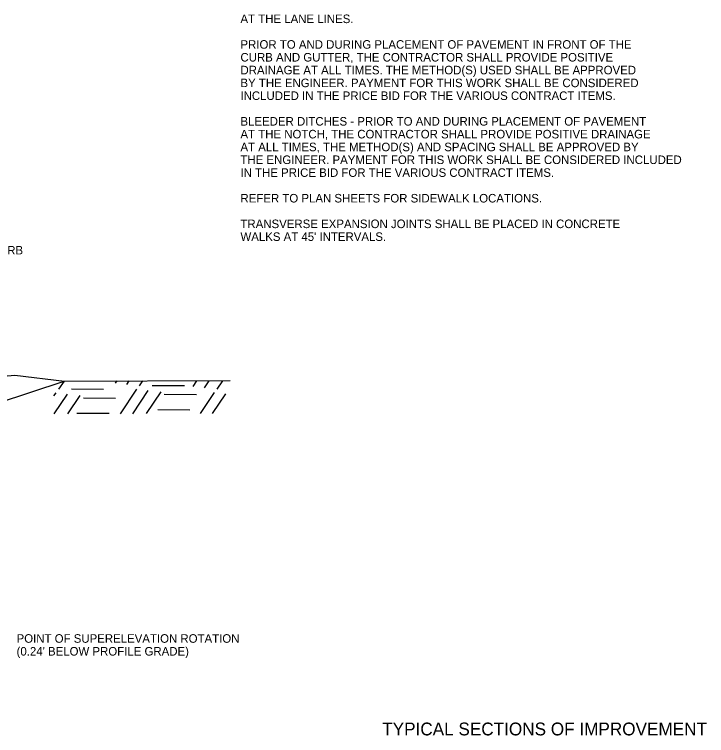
# Model space of a CAD drawing. Extents: x 1001270 to 1003428, y 1840152 to 1842912.
# Drawn here: x 1001377.5 to 1001426.1, y 1841823.6 to 1841874.3 of the extents above; entities that cross this region are included whole.
import ezdxf

# ---------------------------------------------------------------- set-up
doc = ezdxf.new("R2010")
doc.units = 0
doc.layers.add('19', color=7, linetype='Continuous')
doc.layers.add('60', color=7, linetype='Continuous')

msp = doc.modelspace()

# ---------------------------------------------------------------- linework, layer by layer
at = {"layer": '19'}
for p, q in [((1001371.277, 1841845.267), (1001381.016, 1841848.513)), ((1001380.647, 1841847.93), (1001381.038, 1841848.513)), ((1001384.632, 1841848.365), (1001384.738, 1841848.515)), ((1001385.427, 1841848.273), (1001385.593, 1841848.517)), ((1001386.322, 1841848.181), (1001386.548, 1841848.519)), ((1001390.086, 1841848.125), (1001390.348, 1841848.52)), ((1001390.881, 1841848.033), (1001391.213, 1841848.522)), ((1001391.776, 1841847.941), (1001392.157, 1841848.515)), ((1001381.535, 1841847.97), (1001383.795, 1841847.948)), ((1001384.984, 1841846.217), (1001386.136, 1841847.938)), ((1001385.839, 1841846.22), (1001386.931, 1841847.846)), ((1001387.21, 1841848.21), (1001389.47, 1841848.198)), ((1001380.307, 1841847.463), (1001380.461, 1841847.688)), ((1001380.329, 1841846.214), (1001381.256, 1841847.596)), ((1001381.284, 1841846.216), (1001382.151, 1841847.504)), ((1001382.375, 1841847.34), (1001384.635, 1841847.319)), ((1001386.794, 1841846.222), (1001387.826, 1841847.754)), ((1001388.04, 1841847.582), (1001390.31, 1841847.569)), ((1001390.594, 1841846.223), (1001391.59, 1841847.699)), ((1001391.449, 1841846.225), (1001392.385, 1841847.607)), ((1001387.598, 1841846.511), (1001389.858, 1841846.49)), ((1001381.922, 1841846.261), (1001384.193, 1841846.248))]:
    msp.add_line(p, q, dxfattribs=at)
for points in [[(1001315.492, 1841839.152), (1001320.565, 1841839.126), (1001327.257, 1841840.311), (1001329.992, 1841841.299), (1001337.777, 1841842.357), (1001349.804, 1841843.198), (1001361.777, 1841844.165), (1001365.526, 1841844.404), (1001370.117, 1841846.616), (1001372.821, 1841847.53), (1001375.137, 1841848.711), (1001377.563, 1841848.921), (1001381.038, 1841848.513)], [(1001381.038, 1841848.513), (1001392.689, 1841848.548)]]:
    msp.add_lwpolyline(points, dxfattribs=at)

# ---------------------------------------------------------------- texts
for s, p in [('AT THE LANE LINES.', (1001393.401, 1841873.653)), ('PRIOR TO AND DURING PLACEMENT OF PAVEMENT IN FRONT OF THE', (1001393.401, 1841871.853)), ('CURB AND GUTTER, THE CONTRACTOR SHALL PROVIDE POSITIVE', (1001393.401, 1841870.953)), ('DRAINAGE AT ALL TIMES. THE METHOD(S) USED SHALL BE APPROVED', (1001393.401, 1841870.053)), ('BY THE ENGINEER. PAYMENT FOR THIS WORK SHALL BE CONSIDERED', (1001393.401, 1841869.153)), ('INCLUDED IN THE PRICE BID FOR THE VARIOUS CONTRACT ITEMS.', (1001393.401, 1841868.253)), ('BLEEDER DITCHES - PRIOR TO AND DURING PLACEMENT OF PAVEMENT', (1001393.401, 1841866.453)), ('AT THE NOTCH, THE CONTRACTOR SHALL PROVIDE POSITIVE DRAINAGE', (1001393.401, 1841865.553)), ('AT ALL TIMES, THE METHOD(S) AND SPACING SHALL BE APPROVED BY', (1001393.401, 1841864.653)), ('THE ENGINEER. PAYMENT FOR THIS WORK SHALL BE CONSIDERED INCLUDED', (1001393.401, 1841863.753)), ('IN THE PRICE BID FOR THE VARIOUS CONTRACT ITEMS.', (1001393.401, 1841862.853)), ('REFER TO PLAN SHEETS FOR SIDEWALK LOCATIONS.', (1001393.401, 1841861.053)), ('TRANSVERSE EXPANSION JOINTS SHALL BE PLACED IN CONCRETE', (1001393.401, 1841859.253)), ("WALKS AT 45' INTERVALS.", (1001393.401, 1841858.353))]:
    msp.add_text(s, height=0.6, dxfattribs=at).set_placement(p)
for s, rotation, p in [('CONCRETE COMBINATION CURB', 360, (1001365.258, 1841857.4)), ('POINT OF SUPERELEVATION ROTATION', 359.9954, (1001377.683, 1841830.13)), ("(0.24' BELOW PROFILE GRADE)", 359.9954, (1001377.683, 1841829.23))]:
    msp.add_text(s, height=0.6, rotation=rotation, dxfattribs=at).set_placement(p)
at = {"layer": '60'}
msp.add_text('TYPICAL SECTIONS OF IMPROVEMENT', height=0.9, dxfattribs=at).set_placement((1001403.354, 1841823.623))

doc.saveas('drawing.dxf')
